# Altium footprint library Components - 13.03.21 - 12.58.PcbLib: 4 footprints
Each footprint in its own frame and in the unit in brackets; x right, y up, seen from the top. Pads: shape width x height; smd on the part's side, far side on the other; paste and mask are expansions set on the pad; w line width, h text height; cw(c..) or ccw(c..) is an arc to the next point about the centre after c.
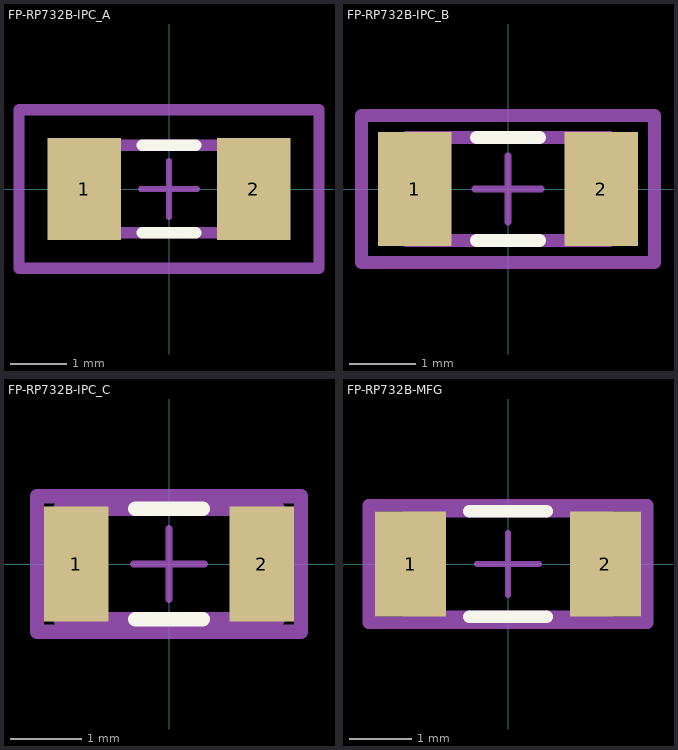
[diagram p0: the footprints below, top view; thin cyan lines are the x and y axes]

## FP-RP732B-IPC_A [mm]
pads (2):
  rect 1.306x1.808 smd paste+0 mask+0: 1(-1.501,0) 2(1.501,0)
Top Overlay:
  lines w0.2: -0.473,-0.775 0.473,-0.775 ; -0.473,0.775 0.473,0.775
Mechanical 5:
  lines w0.2: -2.654,-1.404 2.654,-1.404 2.654,1.404 -2.654,1.404 -2.654,-1.404
  text ".Designator" at 0,0.188 h1
Mechanical 13:
  lines w0.2: -1.525,-0.775 1.525,-0.775 1.525,0.775 -1.525,0.775 -1.525,-0.775
Mechanical 15:
  lines w0.2: -2.654,-1.404 2.654,-1.404 2.654,1.404 -2.654,1.404 -2.654,-1.404
Mechanical 16:
  lines w0.1: -0.5,0 0.5,0 ; 0,-0.5 0,0.5
3D body "Res_TE_Connectivity_RP73D2B30K9BTDF_eec.STEP": height 0.25, standoff 0, extent -2.654,-1.404 2.654,1.404

## FP-RP732B-IPC_B [mm]
pads (2):
  rect 1.106x1.708 smd paste+0 mask+0: 1(-1.401,0) 2(1.401,0)
Top Overlay:
  lines w0.2: -0.473,-0.775 0.473,-0.775 ; -0.473,0.775 0.473,0.775
Mechanical 5:
  lines w0.2: -2.204,-1.104 2.204,-1.104 2.204,1.104 -2.204,1.104 -2.204,-1.104
  text ".Designator" at 0,0.188 h1
Mechanical 13:
  lines w0.2: -1.525,-0.775 1.525,-0.775 1.525,0.775 -1.525,0.775 -1.525,-0.775
Mechanical 15:
  lines w0.2: -2.204,-1.104 2.204,-1.104 2.204,1.104 -2.204,1.104 -2.204,-1.104
Mechanical 16:
  lines w0.1: -0.5,0 0.5,0 ; 0,-0.5 0,0.5
3D body "Res_TE_Connectivity_RP73D2B30K9BTDF_eec.STEP": height 0.25, standoff 0, extent -2.204,-1.104 2.204,1.104

## FP-RP732B-IPC_C [mm]
pads (2):
  rect 0.906x1.608 smd paste+0 mask+0: 1(-1.301,0) 2(1.301,0)
Top Overlay:
  lines w0.2: -0.473,-0.775 0.473,-0.775 ; -0.473,0.775 0.473,0.775
Mechanical 5:
  lines w0.2: -1.854,-0.95 1.854,-0.95 1.854,0.95 -1.854,0.95 -1.854,-0.95
  text ".Designator" at 0,0.188 h1
Mechanical 13:
  lines w0.2: -1.525,-0.775 1.525,-0.775 1.525,0.775 -1.525,0.775 -1.525,-0.775
Mechanical 15:
  lines w0.2: -1.854,-0.95 1.854,-0.95 1.854,0.95 -1.854,0.95 -1.854,-0.95
Mechanical 16:
  lines w0.1: -0.5,0 0.5,0 ; 0,-0.5 0,0.5
3D body "Res_TE_Connectivity_RP73D2B30K9BTDF_eec.STEP": height 0.25, standoff 0, extent -1.854,-0.95 1.854,0.95

## FP-RP732B-MFG [mm]
pads (2):
  rect 1.15x1.7 smd paste+0 mask+0: 1(-1.575,0) 2(1.575,0)
Top Overlay:
  lines w0.2: -0.625,-0.85 0.625,-0.85 ; -0.625,0.85 0.625,0.85
Mechanical 5:
  lines w0.2: -2.25,-0.95 2.25,-0.95 2.25,0.95 -2.25,0.95 -2.25,-0.95
  text ".Designator" at 0,0.188 h1
Mechanical 13:
  lines w0.2: -1.6,-0.85 1.6,-0.85 1.6,0.85 -1.6,0.85 -1.6,-0.85
Mechanical 15:
  lines w0.2: -2.25,-0.95 2.25,-0.95 2.25,0.95 -2.25,0.95 -2.25,-0.95
Mechanical 16:
  lines w0.1: -0.5,0 0.5,0 ; 0,-0.5 0,0.5
3D body "Res_TE_Connectivity_RP73D2B30K9BTDF_eec.STEP": height 0.25, standoff 0, extent -2.25,-0.95 2.25,0.95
